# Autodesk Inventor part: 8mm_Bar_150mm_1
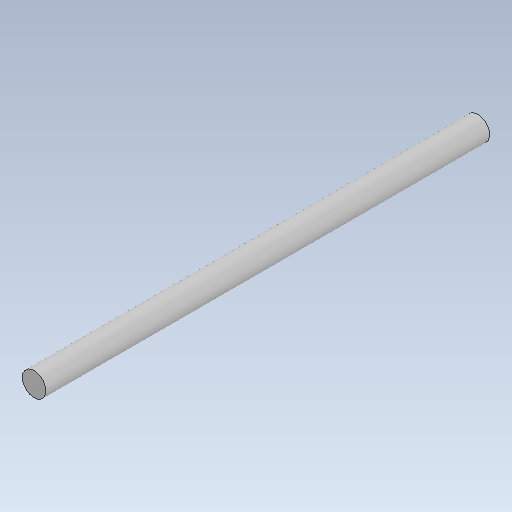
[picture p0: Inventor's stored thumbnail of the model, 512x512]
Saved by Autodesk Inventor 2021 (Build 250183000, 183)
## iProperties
Created: 2026-10
Part Number: 8mm_Bar_150mm_1
Material: Steel
Document SubType Name: Modeling
Designer: hp
Density: 7.85 g/cm^3
Appearance: Default
Author: hp
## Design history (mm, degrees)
feature "Body1"
body "Solid1"
